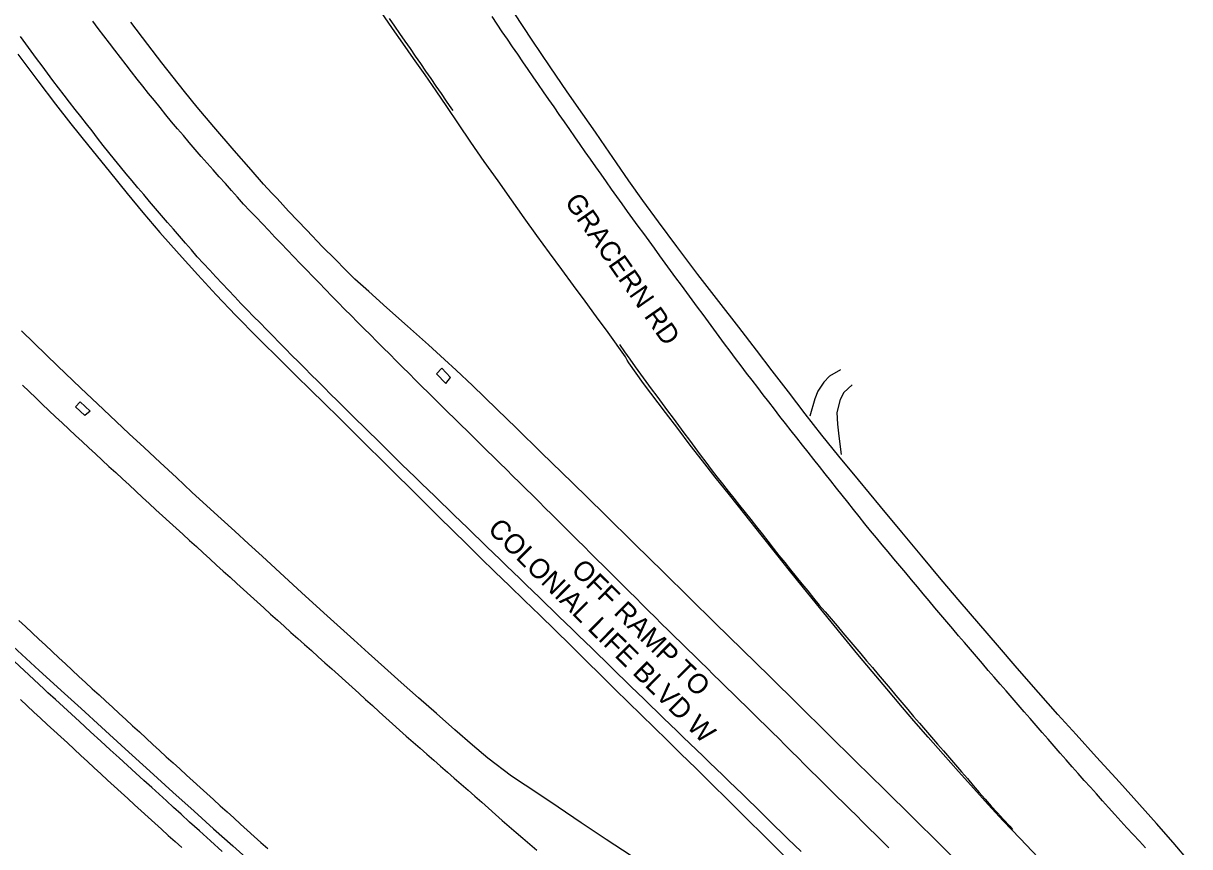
# Model space of a CAD drawing. Extents: x 1948091 to 1975253, y 787267 to 823306.
# Drawn here: x 1971695.9 to 1972015.4, y 795355.2 to 795580.8 of the extents above; entities that cross this region are included whole.
import ezdxf

# ---------------------------------------------------------------- set-up
doc = ezdxf.new("R2010")
doc.units = 0
for name, color, linetype in [('RD_EX_Driveway', 7, 'Continuous'), ('RD_EX_Pavement_Markings', 7, 'Continuous'), ('RD_EX_Road', 7, 'Continuous'), ('RD_TX_RoadID', 7, 'Continuous')]:
    doc.layers.add(name, color=color, linetype=linetype)

msp = doc.modelspace()

# ---------------------------------------------------------------- linework, layer by layer
at = {"layer": 'RD_EX_Driveway'}
for points in [[(1971919.74, 795485.86), (1971916.72, 795484.1), (1971915.19, 795482.48), (1971913.52, 795479.98), (1971912.68, 795477.93), (1971911.36, 795473.2)], [(1971922.93, 795481.72), (1971920.67, 795479.62), (1971919.67, 795477.73), (1971918.75, 795474.14), (1971918.93, 795470.96), (1971919.32, 795467.66), (1971919.88, 795462.66)]]:
    msp.add_lwpolyline(points, dxfattribs=at)
at = {"layer": 'RD_EX_Pavement_Markings'}
for points in [[(1971796.12, 795582.11), (1971797.55, 795580.06), (1971798.97, 795578), (1971800.39, 795575.95), (1971801.81, 795573.89), (1971803.23, 795571.84), (1971804.66, 795569.78), (1971806.08, 795567.73), (1971807.5, 795565.67), (1971808.92, 795563.61), (1971810.34, 795561.55), (1971811.76, 795559.49), (1971813.17, 795557.43), (1971813.52, 795556.93)], [(1972003.29, 795354.87), (1972001.6, 795356.7), (1971999.9, 795358.54), (1971998.21, 795360.37), (1971996.51, 795362.21), (1971994.84, 795364.07), (1971993.18, 795365.94), (1971991.51, 795367.8), (1971989.84, 795369.66), (1971988.18, 795371.53), (1971986.51, 795373.39), (1971984.84, 795375.25), (1971983.18, 795377.12), (1971981.51, 795378.98), (1971979.87, 795380.87), (1971978.24, 795382.76), (1971976.6, 795384.65), (1971974.96, 795386.54), (1971973.32, 795388.42), (1971971.68, 795390.31), (1971970.05, 795392.2), (1971968.41, 795394.09), (1971966.77, 795395.98), (1971965.13, 795397.87), (1971963.5, 795399.76), (1971961.86, 795401.65), (1971960.22, 795403.53), (1971958.59, 795405.43), (1971956.97, 795407.33), (1971955.34, 795409.23), (1971953.72, 795411.13), (1971952.09, 795413.03), (1971950.47, 795414.93), (1971948.84, 795416.83), (1971947.21, 795418.73), (1971945.6, 795420.63), (1971943.99, 795422.55), (1971942.39, 795424.47), (1971940.79, 795426.39), (1971939.19, 795428.31), (1971937.59, 795430.23), (1971935.98, 795432.14), (1971934.38, 795434.06), (1971932.78, 795435.98), (1971931.18, 795437.9), (1971929.57, 795439.82), (1971927.99, 795441.76), (1971926.43, 795443.71), (1971924.87, 795445.66), (1971923.32, 795447.62), (1971921.76, 795449.57), (1971920.2, 795451.53), (1971918.64, 795453.48), (1971917.08, 795455.44), (1971915.52, 795457.39), (1971913.96, 795459.35), (1971912.41, 795461.31), (1971910.87, 795463.27), (1971909.32, 795465.24), (1971907.77, 795467.2), (1971906.23, 795469.16), (1971904.68, 795471.13), (1971903.15, 795473.1), (1971901.62, 795475.09), (1971900.1, 795477.07), (1971898.58, 795479.05), (1971897.05, 795481.03), (1971895.53, 795483.01), (1971894, 795484.99), (1971892.48, 795486.98), (1971890.97, 795488.97), (1971889.48, 795490.98), (1971888, 795492.99), (1971886.52, 795495.01), (1971885.04, 795497.02), (1971883.56, 795499.03), (1971882.07, 795501.05), (1971880.59, 795503.06), (1971879.11, 795505.07), (1971877.63, 795507.09), (1971876.15, 795509.1), (1971874.66, 795511.11), (1971873.18, 795513.13), (1971871.7, 795515.14), (1971870.22, 795517.15), (1971868.75, 795519.18), (1971867.29, 795521.2), (1971865.82, 795523.23), (1971864.35, 795525.25), (1971862.89, 795527.28), (1971861.42, 795529.3), (1971859.95, 795531.33), (1971858.49, 795533.35), (1971857.04, 795535.39), (1971855.6, 795537.43), (1971854.15, 795539.47), (1971852.71, 795541.51), (1971851.26, 795543.55), (1971849.82, 795545.59), (1971848.4, 795547.65), (1971846.97, 795549.7), (1971845.55, 795551.75), (1971844.12, 795553.81), (1971842.7, 795555.86), (1971841.27, 795557.92), (1971839.85, 795559.97), (1971838.42, 795562.02), (1971837.01, 795564.09), (1971835.59, 795566.15), (1971834.18, 795568.21), (1971832.76, 795570.27), (1971831.35, 795572.33), (1971829.93, 795574.39), (1971828.52, 795576.45), (1971827.1, 795578.51), (1971825.69, 795580.57), (1971824.3, 795582.65)], [(1971932.97, 795354.93), (1971931.19, 795356.69), (1971929.41, 795358.44), (1971927.63, 795360.2), (1971925.86, 795361.95), (1971924.08, 795363.71), (1971922.3, 795365.46), (1971920.52, 795367.22), (1971918.74, 795368.97), (1971916.96, 795370.73), (1971915.19, 795372.49), (1971913.42, 795374.25), (1971911.65, 795376.01), (1971909.88, 795377.77), (1971908.11, 795379.54), (1971906.34, 795381.3), (1971904.57, 795383.06), (1971902.8, 795384.82), (1971901.03, 795386.59), (1971899.25, 795388.34), (1971897.46, 795390.09), (1971895.68, 795391.84), (1971893.9, 795393.59), (1971892.11, 795395.34), (1971890.33, 795397.08), (1971888.55, 795398.83), (1971886.76, 795400.58), (1971884.98, 795402.33), (1971883.2, 795404.08), (1971881.41, 795405.82), (1971879.63, 795407.57), (1971877.85, 795409.32), (1971876.06, 795411.07), (1971874.28, 795412.81), (1971872.5, 795414.56), (1971870.71, 795416.31), (1971868.95, 795418.07), (1971867.18, 795419.83), (1971865.41, 795421.59), (1971863.64, 795423.36), (1971861.87, 795425.12), (1971860.1, 795426.88), (1971858.33, 795428.64), (1971856.56, 795430.4), (1971854.79, 795432.16), (1971853.02, 795433.92), (1971851.25, 795435.68), (1971849.48, 795437.45), (1971847.71, 795439.21), (1971845.94, 795440.97), (1971844.17, 795442.73), (1971842.4, 795444.49), (1971840.64, 795446.25), (1971838.87, 795448.01), (1971837.1, 795449.78), (1971835.32, 795451.53), (1971833.54, 795453.28), (1971831.76, 795455.03), (1971829.98, 795456.78), (1971828.2, 795458.53), (1971826.43, 795460.28), (1971824.65, 795462.04), (1971822.87, 795463.79), (1971821.09, 795465.54), (1971819.31, 795467.29), (1971817.53, 795469.04), (1971815.75, 795470.79), (1971813.97, 795472.55), (1971812.19, 795474.3), (1971810.41, 795476.05), (1971808.63, 795477.8), (1971806.86, 795479.56), (1971805.09, 795481.32), (1971803.32, 795483.08), (1971801.56, 795484.85), (1971799.79, 795486.61), (1971798.02, 795488.38), (1971796.26, 795490.14), (1971794.49, 795491.9), (1971792.72, 795493.67), (1971790.95, 795495.43), (1971789.19, 795497.2), (1971787.42, 795498.96), (1971785.65, 795500.72), (1971783.89, 795502.49), (1971782.15, 795504.28), (1971780.41, 795506.08), (1971778.68, 795507.87), (1971776.94, 795509.67), (1971775.21, 795511.46), (1971773.47, 795513.26), (1971771.74, 795515.05), (1971770, 795516.85), (1971768.27, 795518.65), (1971766.55, 795520.45), (1971764.82, 795522.26), (1971763.1, 795524.07), (1971761.37, 795525.87), (1971759.64, 795527.68), (1971757.92, 795529.48), (1971756.2, 795531.29), (1971754.54, 795533.16), (1971752.88, 795535.03), (1971751.23, 795536.89), (1971749.57, 795538.76), (1971747.91, 795540.63), (1971746.25, 795542.5), (1971744.59, 795544.36), (1971742.95, 795546.24), (1971741.33, 795548.14), (1971739.72, 795550.05), (1971738.1, 795551.95), (1971736.48, 795553.85), (1971734.89, 795555.78), (1971733.33, 795557.73), (1971731.78, 795559.68), (1971730.22, 795561.63), (1971728.66, 795563.59), (1971727.11, 795565.54), (1971725.56, 795567.5), (1971724.04, 795569.48), (1971722.51, 795571.46), (1971720.99, 795573.44), (1971719.47, 795575.42), (1971717.95, 795577.4), (1971716.43, 795579.39), (1971714.95, 795581.39)], [(1971908.93, 795353.88), (1971907.14, 795355.62), (1971905.35, 795357.37), (1971903.56, 795359.11), (1971901.77, 795360.86), (1971899.99, 795362.61), (1971898.2, 795364.35), (1971896.42, 795366.1), (1971894.63, 795367.85), (1971892.85, 795369.6), (1971891.06, 795371.34), (1971889.28, 795373.09), (1971887.49, 795374.84), (1971885.69, 795376.57), (1971883.89, 795378.3), (1971882.09, 795380.03), (1971880.28, 795381.76), (1971878.48, 795383.49), (1971876.68, 795385.22), (1971874.88, 795386.95), (1971873.08, 795388.68), (1971871.28, 795390.41), (1971869.48, 795392.15), (1971867.7, 795393.89), (1971865.91, 795395.63), (1971864.12, 795397.38), (1971862.33, 795399.12), (1971860.54, 795400.86), (1971858.75, 795402.6), (1971856.96, 795404.35), (1971855.18, 795406.09), (1971853.39, 795407.83), (1971851.59, 795409.57), (1971849.8, 795411.3), (1971848, 795413.04), (1971846.21, 795414.77), (1971844.42, 795416.51), (1971842.62, 795418.25), (1971840.83, 795419.98), (1971839.04, 795421.72), (1971837.24, 795423.45), (1971835.45, 795425.19), (1971833.66, 795426.93), (1971831.86, 795428.66), (1971830.07, 795430.4), (1971828.28, 795432.13), (1971826.49, 795433.87), (1971824.69, 795435.61), (1971822.9, 795437.34), (1971821.11, 795439.08), (1971819.31, 795440.82), (1971817.52, 795442.55), (1971815.73, 795444.29), (1971813.94, 795446.03), (1971812.15, 795447.77), (1971810.36, 795449.5), (1971808.57, 795451.24), (1971806.77, 795452.98), (1971804.98, 795454.72), (1971803.19, 795456.46), (1971801.4, 795458.2), (1971799.61, 795459.94), (1971797.84, 795461.69), (1971796.06, 795463.44), (1971794.28, 795465.19), (1971792.5, 795466.95), (1971790.72, 795468.7), (1971788.94, 795470.45), (1971787.16, 795472.2), (1971785.38, 795473.95), (1971783.61, 795475.71), (1971781.84, 795477.48), (1971780.07, 795479.24), (1971778.31, 795481), (1971776.54, 795482.77), (1971774.77, 795484.53), (1971773, 795486.29), (1971771.24, 795488.06), (1971769.47, 795489.82), (1971767.7, 795491.58), (1971765.96, 795493.37), (1971764.21, 795495.16), (1971762.47, 795496.94), (1971760.72, 795498.73), (1971758.98, 795500.52), (1971757.24, 795502.3), (1971755.49, 795504.09), (1971753.78, 795505.9), (1971752.07, 795507.73), (1971750.37, 795509.55), (1971748.66, 795511.38), (1971746.96, 795513.2), (1971745.25, 795515.02), (1971743.55, 795516.85), (1971741.91, 795518.73), (1971740.27, 795520.61), (1971738.63, 795522.49), (1971736.99, 795524.38), (1971735.35, 795526.26), (1971733.71, 795528.14), (1971732.09, 795530.04), (1971730.48, 795531.96), (1971728.88, 795533.87), (1971727.28, 795535.78), (1971725.68, 795537.7), (1971724.08, 795539.62), (1971722.48, 795541.54), (1971720.88, 795543.46), (1971719.32, 795545.41), (1971717.79, 795547.38), (1971716.25, 795549.35), (1971714.72, 795551.32), (1971713.18, 795553.29), (1971711.64, 795555.25), (1971710.1, 795557.22), (1971708.57, 795559.19), (1971707.03, 795561.16), (1971705.49, 795563.12), (1971703.98, 795565.12), (1971702.5, 795567.13), (1971701.02, 795569.14), (1971699.54, 795571.15), (1971698.06, 795573.16), (1971696.58, 795575.17), (1971695.13, 795577.21)], [(1971859.16, 795492.81), (1971860.61, 795490.78), (1971862.07, 795488.75), (1971863.53, 795486.72), (1971864.99, 795484.69), (1971866.45, 795482.66), (1971867.91, 795480.63), (1971869.4, 795478.63), (1971870.89, 795476.62), (1971872.38, 795474.61), (1971873.87, 795472.61), (1971875.36, 795470.6), (1971876.86, 795468.59), (1971878.35, 795466.59), (1971879.84, 795464.58), (1971881.33, 795462.58), (1971882.83, 795460.57), (1971884.32, 795458.57), (1971885.85, 795456.59), (1971887.38, 795454.61), (1971888.93, 795452.65), (1971890.48, 795450.69), (1971892.04, 795448.74), (1971893.6, 795446.78), (1971895.16, 795444.83), (1971896.7, 795442.86), (1971898.25, 795440.9), (1971899.79, 795438.93), (1971901.33, 795436.97), (1971902.88, 795435), (1971904.45, 795433.05), (1971906.02, 795431.11), (1971907.6, 795429.17), (1971909.17, 795427.23), (1971910.75, 795425.29), (1971912.33, 795423.35), (1971913.92, 795421.42), (1971915.54, 795419.52), (1971917.16, 795417.61), (1971918.78, 795415.71), (1971920.4, 795413.81), (1971922.02, 795411.91), (1971923.64, 795410), (1971925.26, 795408.09), (1971926.87, 795406.18), (1971928.47, 795404.27), (1971930.08, 795402.35), (1971931.69, 795400.44), (1971933.3, 795398.53), (1971934.91, 795396.61), (1971936.52, 795394.7), (1971938.14, 795392.79), (1971939.77, 795390.9), (1971941.4, 795389.01), (1971943.04, 795387.11), (1971944.67, 795385.22), (1971946.3, 795383.33), (1971947.93, 795381.44), (1971949.57, 795379.54), (1971951.2, 795377.65), (1971952.84, 795375.76), (1971954.48, 795373.87), (1971956.12, 795371.99), (1971957.75, 795370.1), (1971959.39, 795368.21), (1971961.05, 795366.34), (1971962.73, 795364.49), (1971964.41, 795362.64), (1971966.1, 795360.79), (1971966.87, 795359.94)], [(1971695.69, 795481.68), (1971697.5, 795479.95), (1971699.29, 795478.21), (1971701.08, 795476.46), (1971702.87, 795474.72), (1971704.69, 795473.01), (1971706.53, 795471.31), (1971708.36, 795469.61), (1971710.19, 795467.91), (1971712.02, 795466.21), (1971713.85, 795464.51), (1971715.69, 795462.82), (1971717.52, 795461.12), (1971719.35, 795459.42), (1971721.19, 795457.72), (1971723.02, 795456.02), (1971724.86, 795454.33), (1971726.7, 795452.63), (1971728.53, 795450.93), (1971730.37, 795449.24), (1971732.2, 795447.54), (1971734.04, 795445.85), (1971735.89, 795444.16), (1971737.74, 795442.48), (1971739.58, 795440.8), (1971741.43, 795439.12), (1971743.28, 795437.43), (1971745.13, 795435.75), (1971746.98, 795434.07), (1971748.83, 795432.38), (1971750.67, 795430.7), (1971752.52, 795429.02), (1971754.38, 795427.34), (1971756.23, 795425.67), (1971758.08, 795423.99), (1971759.93, 795422.31), (1971761.79, 795420.63), (1971763.64, 795418.95), (1971765.49, 795417.28), (1971767.35, 795415.6), (1971769.21, 795413.93), (1971771.07, 795412.27), (1971772.93, 795410.6), (1971774.8, 795408.93), (1971776.66, 795407.26), (1971778.52, 795405.6), (1971780.38, 795403.93), (1971782.24, 795402.26), (1971784.1, 795400.59), (1971785.95, 795398.91), (1971787.8, 795397.23), (1971789.66, 795395.55), (1971791.51, 795393.87), (1971793.36, 795392.2), (1971795.21, 795390.52), (1971797.06, 795388.84), (1971798.92, 795387.17), (1971800.8, 795385.52), (1971802.68, 795383.87), (1971804.56, 795382.22), (1971806.43, 795380.57), (1971808.31, 795378.92), (1971810.19, 795377.27), (1971812.06, 795375.62), (1971813.94, 795373.96), (1971815.82, 795372.31), (1971817.7, 795370.67), (1971819.58, 795369.02), (1971821.45, 795367.37), (1971823.33, 795365.72), (1971825.21, 795364.07), (1971827.09, 795362.42), (1971828.97, 795360.77), (1971830.86, 795359.13), (1971832.75, 795357.5), (1971834.65, 795355.87), (1971836.54, 795354.24)], [(1971694.68, 795417.22), (1971696.5, 795415.51), (1971698.33, 795413.81), (1971700.15, 795412.1), (1971701.98, 795410.39), (1971703.8, 795408.68), (1971705.63, 795406.98), (1971707.46, 795405.27), (1971709.28, 795403.56), (1971711.11, 795401.85), (1971712.95, 795400.16), (1971714.79, 795398.47), (1971716.63, 795396.78), (1971718.47, 795395.09), (1971720.31, 795393.4), (1971722.15, 795391.71), (1971723.99, 795390.02), (1971725.83, 795388.33), (1971727.67, 795386.64), (1971729.51, 795384.95), (1971731.36, 795383.25), (1971733.2, 795381.56), (1971735.04, 795379.87), (1971736.89, 795378.19), (1971738.74, 795376.51), (1971740.59, 795374.83), (1971742.44, 795373.15), (1971744.29, 795371.47), (1971746.14, 795369.79), (1971747.99, 795368.11), (1971749.84, 795366.43), (1971751.69, 795364.75), (1971753.54, 795363.07), (1971755.39, 795361.39), (1971757.24, 795359.71), (1971759.11, 795358.04), (1971760.97, 795356.38), (1971762.84, 795354.72)], [(1971695.11, 795395.51), (1971696.95, 795393.81), (1971698.78, 795392.11), (1971700.61, 795390.41), (1971702.45, 795388.72), (1971704.28, 795387.02), (1971706.12, 795385.32), (1971707.96, 795383.63), (1971709.79, 795381.93), (1971711.63, 795380.24), (1971713.46, 795378.54), (1971715.3, 795376.84), (1971717.14, 795375.15), (1971718.97, 795373.45), (1971720.81, 795371.76), (1971722.66, 795370.08), (1971724.51, 795368.39), (1971726.35, 795366.7), (1971728.2, 795365.02), (1971730.04, 795363.33), (1971731.89, 795361.66), (1971733.75, 795359.98), (1971735.6, 795358.3), (1971737.46, 795356.63), (1971739.31, 795354.95)]]:
    msp.add_lwpolyline(points, dxfattribs=at)
at = {"layer": 'RD_EX_Road'}
for points in [[(1971973.91, 795352.22), (1971968.98, 795357.42), (1971964.33, 795362.3), (1971960.22, 795366.74), (1971956.27, 795371.11), (1971952.1, 795375.81), (1971947.88, 795380.6), (1971943.77, 795385.24), (1971939.83, 795389.73), (1971936.75, 795393.32), (1971932.4, 795398.47), (1971928.42, 795403.19), (1971924.47, 795407.9), (1971920.85, 795412.3), (1971917.2, 795416.78), (1971913.15, 795421.75), (1971909.19, 795426.63), (1971905.8, 795430.85), (1971902.3, 795435.25), (1971898.02, 795440.65), (1971893.51, 795446.33), (1971889.31, 795451.59), (1971885.43, 795456.44), (1971881.89, 795460.92), (1971878.52, 795465.27), (1971875.13, 795469.76), (1971871.8, 795474.18), (1971865.75, 795482.13), (1971861.78, 795487.75), (1971861.33, 795488.49), (1971860.83, 795489.47), (1971856.06, 795496.07), (1971852.88, 795500.39), (1971849.75, 795504.68), (1971846.59, 795509.01), (1971843.37, 795513.4), (1971840.02, 795517.96), (1971836.53, 795522.69), (1971833.05, 795527.52), (1971829.58, 795532.46), (1971825.94, 795537.62), (1971822.15, 795542.97), (1971818.5, 795548.23), (1971815.06, 795553.31), (1971811.91, 795558.01), (1971808.99, 795562.35), (1971805.96, 795566.73), (1971802.81, 795571.17), (1971799.84, 795575.37), (1971797.01, 795579.41), (1971793.78, 795584.1)], [(1972015.38, 795351.08), (1972010.82, 795356.38), (1972006.33, 795361.52), (1972001.68, 795366.73), (1971996.17, 795372.85), (1971989.89, 795379.77), (1971984.26, 795385.97), (1971979.3, 795391.43), (1971973.96, 795397.47), (1971968.17, 795404.14), (1971962.7, 795410.47), (1971957.61, 795416.38), (1971952.52, 795422.33), (1971947.34, 795428.44), (1971942.04, 795434.79), (1971936.58, 795441.42), (1971930.73, 795448.45), (1971924.63, 795455.73), (1971919.26, 795462.24), (1971914.66, 795467.96), (1971910.09, 795473.8), (1971905.47, 795479.83), (1971901.04, 795485.62), (1971896.72, 795491.23), (1971891.86, 795497.52), (1971886.41, 795504.58), (1971880.69, 795512.03), (1971874.9, 795519.66), (1971869.84, 795526.43), (1971865.58, 795532.26), (1971861.76, 795537.62), (1971858.34, 795542.58), (1971855.34, 795546.97), (1971852.59, 795550.97), (1971849.13, 795555.95), (1971844.89, 795562.07), (1971840.23, 795568.86), (1971835.28, 795576.17), (1971830.33, 795583.66)], [(1971954.65, 795348.35), (1971947.08, 795355.78), (1971939.45, 795363.28), (1971931.75, 795370.85), (1971923.98, 795378.51), (1971916.13, 795386.25), (1971908.2, 795394.07), (1971900.36, 795401.81), (1971892.77, 795409.28), (1971885.44, 795416.49), (1971878.36, 795423.44), (1971871.13, 795430.52), (1971863.37, 795438.13), (1971855.05, 795446.28), (1971846.2, 795454.97), (1971837.83, 795463.17), (1971830.96, 795469.87), (1971825.61, 795475.08), (1971818.89, 795481.54), (1971814.43, 795485.78), (1971811.29, 795488.73), (1971806.89, 795492.7), (1971801.09, 795497.86), (1971795.5, 795502.84), (1971790.49, 795507.31), (1971786.74, 795510.76), (1971784.13, 795513.3), (1971781.27, 795516.16), (1971777.88, 795519.61), (1971773.54, 795524.14), (1971768.57, 795529.39), (1971765.38, 795532.78), (1971763.94, 795534.32), (1971761.71, 795536.78), (1971758.26, 795540.65), (1971753.61, 795545.97), (1971748.06, 795552.42), (1971743.48, 795557.86), (1971740.03, 795562.1), (1971736.92, 795566.03), (1971733.87, 795569.97), (1971729.99, 795575.04), (1971725.35, 795581.14)], [(1971694.41, 795572.33), (1971699.87, 795565.06), (1971704.72, 795558.71), (1971708.94, 795553.26), (1971713.83, 795547.12), (1971719.36, 795540.28), (1971724.29, 795534.22), (1971728.58, 795529), (1971733.31, 795523.49), (1971738.55, 795517.59), (1971743.69, 795511.9), (1971748.73, 795506.45), (1971754.12, 795500.78), (1971760.02, 795494.75), (1971766.84, 795487.95), (1971770.63, 795484.25), (1971774.53, 795480.43), (1971778.43, 795476.61), (1971782.31, 795472.77), (1971786.19, 795468.93), (1971790.07, 795465.08), (1971793.99, 795461.2), (1971797.93, 795457.3), (1971801.9, 795453.38), (1971805.85, 795449.47), (1971809.74, 795445.63), (1971813.58, 795441.85), (1971817.35, 795438.12), (1971821.15, 795434.39), (1971825.05, 795430.56), (1971829.06, 795426.66), (1971833.17, 795422.67), (1971837.35, 795418.62), (1971841.54, 795414.53), (1971845.76, 795410.4), (1971850.01, 795406.23), (1971854.14, 795402.16), (1971858.05, 795398.32), (1971865.16, 795391.33), (1971872.21, 795384.42), (1971876.04, 795380.67), (1971880.07, 795376.71), (1971884.35, 795372.5), (1971888.93, 795367.98), (1971893.81, 795363.15), (1971898.98, 795358), (1971904.34, 795352.66)], [(1971862.37, 795352.67), (1971855.57, 795357.2), (1971848.71, 795361.77), (1971842.36, 795366.02), (1971837.06, 795369.56), (1971829.63, 795374.55), (1971823.09, 795379.5), (1971818.89, 795383), (1971814.08, 795387.19), (1971809.04, 795391.67), (1971804.16, 795396.01), (1971799.42, 795400.24), (1971794.84, 795404.35), (1971790.47, 795408.27), (1971786.39, 795411.93), (1971779.08, 795418.51), (1971772.18, 795424.77), (1971764.97, 795431.39), (1971761.27, 795434.8), (1971757.56, 795438.22), (1971753.81, 795441.65), (1971750.04, 795445.08), (1971746.17, 795448.63), (1971742.09, 795452.37), (1971737.82, 795456.33), (1971733.35, 795460.49), (1971728.96, 795464.59), (1971724.92, 795468.37), (1971717.87, 795474.98), (1971711.57, 795480.95), (1971705.36, 795486.91), (1971698.87, 795493.21), (1971695.36, 795496.6)], [(1971812.87, 795483.79), (1971810.52, 795486.33), (1971809.03, 795484.73), (1971811.61, 795482.09), (1971812.87, 795483.79)], [(1971711.44, 795477.06), (1971714.22, 795474.58), (1971712.72, 795473.36), (1971710.16, 795475.7), (1971711.44, 795477.06)], [(1971693.1, 795410.04), (1971700.24, 795403.46), (1971707.16, 795397.2), (1971711.76, 795393.03), (1971717.31, 795387.96), (1971723.81, 795382.02), (1971730.56, 795375.86), (1971736.83, 795370.16), (1971742.64, 795364.91), (1971747.97, 795360.12), (1971753.24, 795355.41), (1971758.85, 795350.39)], [(1971750.39, 795353.9), (1971747.14, 795356.82), (1971744.14, 795359.53), (1971741.45, 795361.96), (1971739.08, 795364.12), (1971737.02, 795365.99), (1971735.09, 795367.76), (1971733.1, 795369.58), (1971731.05, 795371.45), (1971728.93, 795373.37), (1971726.73, 795375.36), (1971724.46, 795377.42), (1971722.11, 795379.57), (1971719.68, 795381.79), (1971717.09, 795384.15), (1971714.28, 795386.72), (1971711.25, 795389.5), (1971707.99, 795392.49), (1971704.72, 795395.5), (1971702.64, 795397.41), (1971701.64, 795398.33), (1971698.77, 795400.98), (1971696.09, 795403.46), (1971693.45, 795405.91)]]:
    msp.add_lwpolyline(points, dxfattribs=at)

# ---------------------------------------------------------------- texts
at = {"layer": 'RD_TX_RoadID'}
for s, rotation, p in [('GRACERN RD', 304.8214, (1971844, 795531.91)), ('COLONIAL LIFE BLVD W', 315.2975, (1971822.84, 795441.91)), ('OFF RAMP TO', 315.2975, (1971845.67, 795430.71))]:
    msp.add_text(s, height=5.4, rotation=rotation, dxfattribs=at).set_placement(p)

doc.saveas('drawing.dxf')
